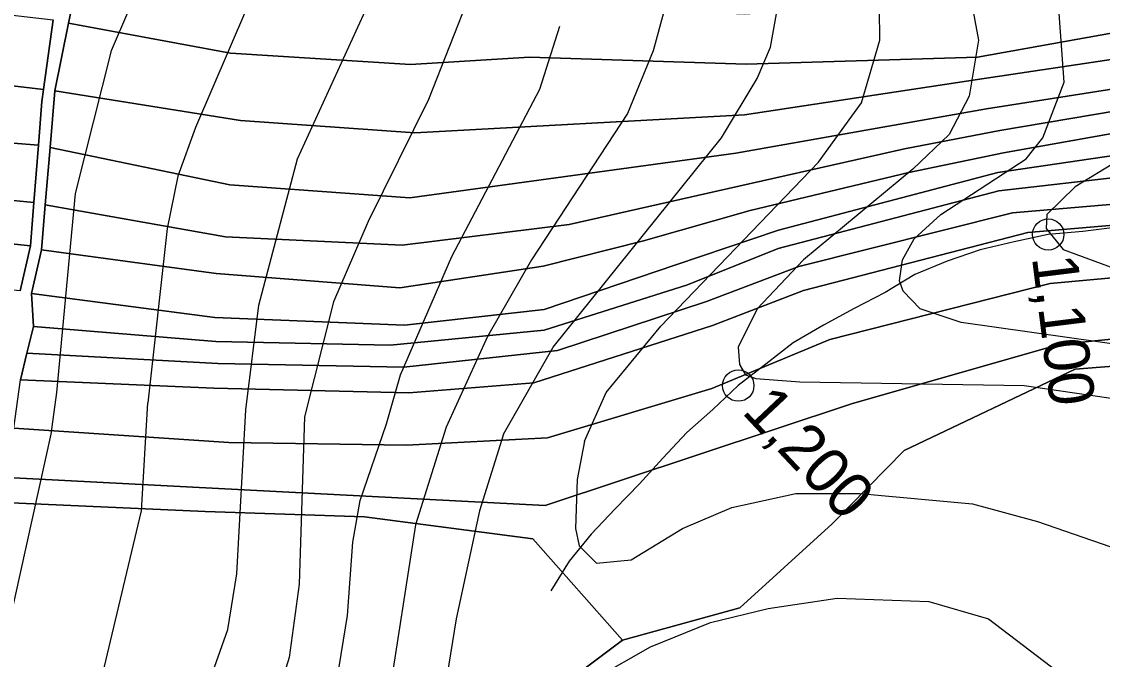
# Model space of a CAD drawing. Extents: x -510989 to -501240, y -1184665 to -1176098.
# Drawn here: x -510646.9 to -510337, y -1180937.6 to -1180754.7 of the extents above; entities that cross this region are included whole.
import ezdxf

# ---------------------------------------------------------------- set-up
doc = ezdxf.new("R2010")
doc.units = 0
for name, color, linetype in [('lesni_pozemek', 7, 'Continuous'), ('ostatni_plocha_x_ostatni_komunikace', 7, 'Continuous'), ('trasovani_toku', 7, 'Continuous'), ('vrstevnice_01', 7, 'Continuous'), ('vrstevnice_02', 7, 'Continuous')]:
    doc.layers.add(name, color=color, linetype=linetype)

msp = doc.modelspace()

# ---------------------------------------------------------------- linework, layer by layer
at = {"layer": 'lesni_pozemek'}
for points in [[(-510333.96, -1180757.86), (-510372.8, -1180764.87), (-510439.15, -1180766.86), (-510501.25, -1180764.87), (-510535.35, -1180767), (-510587, -1180763.69), (-510633.43, -1180755.12), (-510630.61, -1180741.23), (-510584.22, -1180746.54), (-510500.84, -1180749.96), (-510439.58, -1180752.46), (-510376.49, -1180748.63), (-510329.89, -1180740.89)], [(-510326.24, -1180764.25), (-510372.87, -1180771.28), (-510439.64, -1180781.36), (-510534.17, -1180786.58), (-510584.11, -1180783.03), (-510637.37, -1180774.48), (-510633.43, -1180755.12), (-510587, -1180763.69), (-510535.35, -1180767), (-510501.25, -1180764.87), (-510439.15, -1180766.86), (-510372.8, -1180764.87), (-510333.96, -1180757.86)], [(-510317.28, -1180771.36), (-510370.26, -1180779.68), (-510442.11, -1180792.41), (-510535.6, -1180805.23), (-510587.18, -1180801.43), (-510638.74, -1180790.8), (-510637.37, -1180774.48), (-510584.11, -1180783.03), (-510534.17, -1180786.58), (-510439.64, -1180781.36), (-510372.87, -1180771.28), (-510326.24, -1180764.25)], [(-510326.3, -1180779.13), (-510366.46, -1180785.85), (-510393.75, -1180791.1), (-510441.24, -1180801.85), (-510489.86, -1180812.86), (-510537.82, -1180818.75), (-510588.43, -1180816.35), (-510640.11, -1180807.17), (-510638.74, -1180790.8), (-510587.18, -1180801.43), (-510535.6, -1180805.23), (-510442.11, -1180792.41), (-510370.26, -1180779.68), (-510317.28, -1180771.36)], [(-510331.53, -1180786.23), (-510365.42, -1180792.33), (-510392.48, -1180797.95), (-510438, -1180808.85), (-510468.55, -1180817.53), (-510497.35, -1180824.82), (-510538.42, -1180830.98), (-510591.11, -1180826.91), (-510641.2, -1180820.14), (-510640.11, -1180807.17), (-510588.43, -1180816.35), (-510537.82, -1180818.75), (-510489.86, -1180812.86), (-510441.24, -1180801.85), (-510393.75, -1180791.1), (-510366.46, -1180785.85), (-510326.3, -1180779.13)], [(-510329.89, -1180792.47), (-510366.98, -1180797.95), (-510429.85, -1180814.43), (-510459.35, -1180824.43), (-510497.07, -1180837.22), (-510537.16, -1180841.72), (-510591.53, -1180839.52), (-510644.05, -1180832.61), (-510641.2, -1180820.14), (-510591.11, -1180826.91), (-510538.42, -1180830.98), (-510497.35, -1180824.82), (-510468.55, -1180817.53), (-510438, -1180808.85), (-510392.48, -1180797.95), (-510365.42, -1180792.33), (-510331.53, -1180786.23)], [(-510310.84, -1180796.76), (-510366.74, -1180803.21), (-510430.02, -1180819.69), (-510456.02, -1180830.17), (-510497.05, -1180843.13), (-510541.18, -1180847.42), (-510591.24, -1180846.41), (-510643.5, -1180842.09), (-510644.05, -1180832.61), (-510591.53, -1180839.52), (-510537.16, -1180841.72), (-510497.07, -1180837.22), (-510459.35, -1180824.43), (-510429.85, -1180814.43), (-510366.98, -1180797.95), (-510329.89, -1180792.47)], [(-510514.43, -1181142.06), (-510517.98, -1181134.4), (-510508.44, -1181129.48), (-510404.8, -1181065.45), (-510385.65, -1181068.79), (-510371.58, -1181065.33), (-510393.83, -1181031.6), (-510459.24, -1181070.48), (-510481.08, -1181080.51), (-510502.03, -1181079.72), (-510527.59, -1181080.7), (-510537.43, -1181072.51), (-510537.49, -1181058.5), (-510515.88, -1181037.1), (-510514.5, -1181030.02), (-510499.76, -1181009.72), (-510504.99, -1180978.68), (-510510.55, -1180959.04), (-510474.66, -1180932.03), (-510440.93, -1180922.79), (-510414.47, -1180898.71), (-510393.89, -1180877.67), (-510344.82, -1180854.38), (-510289.06, -1180849.97)], [(-510652, -1180892.55), (-510594.26, -1180895.19), (-510548.57, -1180896.69), (-510500.31, -1180903.02), (-510474.66, -1180932.03), (-510510.55, -1180959.04), (-510504.99, -1180978.68), (-510499.76, -1181009.72), (-510514.5, -1181030.02), (-510515.88, -1181037.1), (-510537.49, -1181058.5), (-510537.43, -1181072.51), (-510527.59, -1181080.7), (-510502.03, -1181079.72), (-510481.08, -1181080.51), (-510459.24, -1181070.48), (-510393.83, -1181031.6), (-510371.58, -1181065.33), (-510385.65, -1181068.79), (-510404.8, -1181065.45), (-510508.44, -1181129.48), (-510517.98, -1181134.4), (-510514.43, -1181142.06)]]:
    msp.add_lwpolyline(points, dxfattribs=at)
for points in [[(-510689.28, -1180748.14), (-510637.81, -1180754.19), (-510640.58, -1180774.09), (-510688.39, -1180768.49)], [(-510688.18, -1180773.2), (-510688.39, -1180768.49), (-510640.58, -1180774.09), (-510641.06, -1180777.54), (-510642.06, -1180790.1), (-510690.23, -1180786.24)], [(-510083.86, -1180780.95), (-510087.2, -1180785.84), (-510092.01, -1180791.3), (-510135.1, -1180793.22), (-510181.81, -1180796.4), (-510246.56, -1180799.57), (-510362.75, -1180809.46), (-510424.09, -1180824.9), (-510450.56, -1180834.94), (-510493.29, -1180848.99), (-510537.28, -1180853.76), (-510590.68, -1180852.68), (-510645.38, -1180849.79), (-510643.5, -1180842.09), (-510591.24, -1180846.41), (-510541.18, -1180847.42), (-510497.05, -1180843.13), (-510456.02, -1180830.17), (-510430.02, -1180819.69), (-510366.74, -1180803.21), (-510310.84, -1180796.76), (-510251.52, -1180791.01), (-510187.68, -1180788.81), (-510136.65, -1180785.5)], [(-510690.23, -1180786.24), (-510642.06, -1180790.1), (-510643.37, -1180806.5), (-510692.67, -1180801.79)], [(-510092.07, -1180791.37), (-510093.08, -1180792.66), (-510094.49, -1180794.45), (-510097.88, -1180798.76), (-510183.93, -1180803.19), (-510246.73, -1180805.6), (-510358.36, -1180815.11), (-510422.69, -1180831.74), (-510448.85, -1180841.81), (-510500.01, -1180858.29), (-510535.85, -1180861.12), (-510591.76, -1180859.76), (-510647.26, -1180857.42), (-510645.38, -1180849.79), (-510590.68, -1180852.68), (-510537.28, -1180853.76), (-510493.29, -1180848.99), (-510450.56, -1180834.94), (-510424.09, -1180824.9), (-510362.75, -1180809.46), (-510246.56, -1180799.57), (-510181.81, -1180796.4), (-510135.1, -1180793.22), (-510092.01, -1180791.3)], [(-510097.88, -1180798.76), (-510105.89, -1180808.96), (-510110.33, -1180814.6), (-510111.28, -1180814.69), (-510144.01, -1180817.74), (-510168.24, -1180817.57), (-510226.42, -1180819.08), (-510281.07, -1180823.3), (-510352.02, -1180829.82), (-510415.17, -1180845.81), (-510448.99, -1180859.86), (-510496.11, -1180874.04), (-510536.55, -1180876.1), (-510587.44, -1180875.37), (-510649.14, -1180871.3), (-510647.26, -1180857.42), (-510591.76, -1180859.76), (-510535.85, -1180861.12), (-510500.01, -1180858.29), (-510448.85, -1180841.81), (-510422.69, -1180831.74), (-510358.36, -1180815.11), (-510246.73, -1180805.6), (-510183.93, -1180803.19)], [(-510643.37, -1180806.5), (-510644.37, -1180818.98), (-510694.54, -1180813.7), (-510692.67, -1180801.79)], [(-510694.54, -1180813.7), (-510644.37, -1180818.98), (-510647.33, -1180831.84), (-510696.68, -1180827.28)], [(-510111.28, -1180814.69), (-510117.56, -1180832.73), (-510228.98, -1180834.99), (-510284.05, -1180840.6), (-510349.44, -1180847.27), (-510408.67, -1180864.16), (-510496.83, -1180893.47), (-510651.04, -1180885.39), (-510649.14, -1180871.3), (-510587.44, -1180875.37), (-510536.55, -1180876.1), (-510496.11, -1180874.04), (-510448.99, -1180859.86), (-510415.17, -1180845.81), (-510352.02, -1180829.82), (-510281.07, -1180823.3), (-510226.42, -1180819.08), (-510168.24, -1180817.57), (-510144.01, -1180817.74)], [(-510117.56, -1180832.73), (-510130.49, -1180841.99), (-510139.22, -1180844.61), (-510162.73, -1180843.17), (-510222.3, -1180843.41), (-510265.47, -1180846.19), (-510289.06, -1180849.97), (-510344.82, -1180854.38), (-510393.89, -1180877.67), (-510414.47, -1180898.71), (-510440.93, -1180922.79), (-510474.66, -1180932.03), (-510500.31, -1180903.02), (-510548.57, -1180896.69), (-510594.26, -1180895.19), (-510652, -1180892.55), (-510651.04, -1180885.39), (-510496.83, -1180893.47), (-510408.67, -1180864.16), (-510349.44, -1180847.27), (-510284.05, -1180840.6), (-510228.98, -1180834.99)]]:
    msp.add_lwpolyline(points, close=True, dxfattribs=at)
at = {"layer": 'ostatni_plocha_x_ostatni_komunikace'}
for points in [[(-510630.61, -1180741.23), (-510633.43, -1180755.12), (-510637.37, -1180774.48), (-510638.74, -1180790.8), (-510640.11, -1180807.17), (-510641.2, -1180820.14), (-510644.05, -1180832.61), (-510643.5, -1180842.09), (-510645.38, -1180849.79), (-510647.26, -1180857.42)], [(-510647.33, -1180831.84), (-510644.37, -1180818.98), (-510643.37, -1180806.5), (-510642.06, -1180790.1), (-510641.06, -1180777.54), (-510640.58, -1180774.09), (-510637.81, -1180754.19)]]:
    msp.add_lwpolyline(points, dxfattribs=at)
at = {"layer": 'trasovani_toku'}
for p, q in [((-510342.6, -1180814.84), (-510352.56, -1180815.71)), ((-510332.67, -1180813.66), (-510342.6, -1180814.84)), ((-510362.33, -1180817.85), (-510372.06, -1180820.15)), ((-510352.56, -1180815.71), (-510362.33, -1180817.85)), ((-510372.06, -1180820.15), (-510381.53, -1180823.36)), ((-510381.53, -1180823.36), (-510390.76, -1180827.22)), ((-510390.76, -1180827.22), (-510399.35, -1180832.34)), ((-510399.35, -1180832.34), (-510408.2, -1180836.99)), ((-510408.2, -1180836.99), (-510417.02, -1180841.71)), ((-510417.02, -1180841.71), (-510425.64, -1180846.77)), ((-510425.64, -1180846.77), (-510433.5, -1180852.95)), ((-510433.5, -1180852.95), (-510441.43, -1180859.05)), ((-510441.43, -1180859.05), (-510448.72, -1180865.89)), ((-510448.72, -1180865.89), (-510456.2, -1180872.53)), ((-510456.2, -1180872.53), (-510463.02, -1180879.85)), ((-510463.02, -1180879.85), (-510469.75, -1180887.24)), ((-510469.75, -1180887.24), (-510476.71, -1180894.42)), ((-510476.71, -1180894.42), (-510483.57, -1180901.7)), ((-510483.57, -1180901.7), (-510489.95, -1180909.4)), ((-510489.95, -1180909.4), (-510495.19, -1180917.91))]:
    msp.add_line(p, q, dxfattribs=at)
for centre in [(-510352.56, -1180815.71), (-510441.43, -1180859.05)]:
    msp.add_circle(centre, 4.5, dxfattribs=at)
at = {"layer": 'vrstevnice_01'}
for points in [[(-510582.59, -1180866), (-510578.91, -1180836), (-510567.81, -1180794), (-510546.81, -1180748), (-510531.19, -1180695), (-510523, -1180676), (-510516.19, -1180666), (-510494.59, -1180637), (-510486.59, -1180623), (-510480.19, -1180603), (-510471, -1180558)], [(-510549.5, -1180565), (-510550.19, -1180590), (-510553.81, -1180608), (-510561.5, -1180625), (-510580.81, -1180660), (-510590.19, -1180682), (-510601.09, -1180716), (-510621.19, -1180763), (-510631.5, -1180804), (-510636.91, -1180861)], [(-510508.69, -1180873), (-510494.5, -1180848), (-510446.19, -1180788), (-510436, -1180771), (-510432.19, -1180762), (-510429.5, -1180747), (-510432.19, -1180724), (-510429.69, -1180710), (-510410.31, -1180669), (-510400.91, -1180656), (-510391, -1180651), (-510381.09, -1180651), (-510365, -1180658), (-510335.5, -1180675)], [(-510310.5, -1180727), (-510337.19, -1180717), (-510363.59, -1180705), (-510372.59, -1180703), (-510381.81, -1180704), (-510384.59, -1180707), (-510386.81, -1180713), (-510386.09, -1180719), (-510375.69, -1180743), (-510372.59, -1180760), (-510375.19, -1180776), (-510381, -1180787), (-510391.41, -1180797), (-510422.69, -1180823), (-510436, -1180837), (-510441.41, -1180848), (-510441.09, -1180853), (-510439.31, -1180856), (-510436.41, -1180857), (-510423.81, -1180858), (-510359.41, -1180859), (-510325.31, -1180864)], [(-510542.31, -1180870), (-510538.31, -1180856), (-510523.5, -1180822), (-510498.31, -1180774), (-510492.54, -1180755.96)], [(-510329.91, -1180793), (-510344.81, -1180802), (-510352.91, -1180810), (-510353.19, -1180814), (-510348.31, -1180820), (-510331.91, -1180826)], [(-510636.91, -1180861), (-510638.5, -1180873), (-510650.69, -1180928), (-510659.5, -1180947), (-510675, -1180972), (-510681.41, -1180987), (-510693.09, -1181020), (-510700.09, -1181035), (-510707.5, -1181059), (-510709.31, -1181087), (-510705.81, -1181106), (-510699.81, -1181122), (-510689.91, -1181139)], [(-510594.81, -1180949), (-510587.81, -1180929), (-510585.19, -1180913), (-510582.59, -1180866)], [(-510558.81, -1180958), (-510553.5, -1180925), (-510551.91, -1180904), (-510549.81, -1180892), (-510542.31, -1180870)], [(-510508.69, -1180873), (-510515.59, -1180895), (-510522.31, -1180926), (-510528.09, -1180962), (-510535.31, -1180981), (-510536.31, -1180989), (-510534.19, -1180991), (-510529.19, -1180991), (-510518, -1180983), (-510499, -1180957), (-510482.31, -1180943), (-510466.59, -1180934), (-510449.41, -1180927), (-510432.81, -1180923), (-510413.09, -1180920), (-510386.81, -1180921), (-510369.69, -1180926), (-510350, -1180941), (-510340.69, -1180962), (-510323.31, -1181047)]]:
    msp.add_lwpolyline(points, dxfattribs=at)
at = {"layer": 'vrstevnice_02'}
for points in [[(-510514.31, -1180579), (-510517.91, -1180603), (-510523.19, -1180618), (-510548.09, -1180659), (-510562.59, -1180688), (-510577.69, -1180740), (-510597, -1180785), (-510602.09, -1180799), (-510605.19, -1180814), (-510610.69, -1180864)], [(-510262.5, -1180577), (-510271.91, -1180585), (-510285.91, -1180601), (-510301.41, -1180624), (-510309.41, -1180632), (-510315.59, -1180636), (-510324.09, -1180638), (-510333.91, -1180636), (-510363.19, -1180626), (-510386.09, -1180621), (-510399.91, -1180624), (-510406.19, -1180626), (-510414.59, -1180633), (-510429.69, -1180659), (-510447.41, -1180693), (-510453.81, -1180708), (-510459, -1180738), (-510465.81, -1180763), (-510473.19, -1180781), (-510500.69, -1180823), (-510513.31, -1180845), (-510525.19, -1180871)], [(-510447.59, -1180580), (-510462.31, -1180626), (-510476.31, -1180655), (-510495.69, -1180684), (-510510.41, -1180720), (-510512.19, -1180731), (-510530.19, -1180777), (-510547.5, -1180812), (-510557.5, -1180835), (-510565.81, -1180868)], [(-510485.5, -1180875), (-510479.31, -1180861), (-510463.59, -1180842), (-510418.41, -1180795), (-510406.09, -1180778), (-510400.81, -1180760), (-510400.91, -1180751), (-510407.81, -1180728), (-510408.31, -1180711), (-510406.5, -1180704), (-510397.69, -1180687), (-510390.41, -1180679), (-510379, -1180675), (-510365.41, -1180680), (-510337.19, -1180695), (-510322.69, -1180701)], [(-510306.59, -1180851), (-510377.5, -1180841), (-510389.31, -1180837), (-510394.19, -1180832), (-510395.19, -1180829), (-510394.31, -1180823), (-510391, -1180817), (-510383.31, -1180810), (-510358.91, -1180794), (-510354.09, -1180788), (-510348, -1180772), (-510349.81, -1180747), (-510348, -1180741), (-510345.09, -1180739), (-510336, -1180740)], [(-510540.91, -1181140), (-510612.5, -1181135), (-510644.81, -1181139), (-510661.59, -1181135), (-510670.09, -1181126), (-510675.59, -1181113), (-510677.81, -1181103), (-510679.59, -1181084), (-510672, -1181058), (-510656.31, -1181024), (-510644.09, -1180987), (-510630.41, -1180959), (-510623.19, -1180940), (-510612.5, -1180895), (-510610.69, -1180864)], [(-510565.81, -1180868), (-510567.31, -1180916), (-510570.19, -1180937), (-510573.91, -1180949)], [(-510525.19, -1180871), (-510534, -1180899), (-510541.91, -1180950)], [(-510485.5, -1180875), (-510487.59, -1180886), (-510488.09, -1180900), (-510487, -1180905), (-510482.09, -1180910), (-510472.09, -1180909), (-510457.41, -1180900), (-510443.31, -1180894), (-510424.91, -1180890), (-510406.59, -1180890), (-510374.31, -1180893), (-510355.59, -1180898), (-510329.59, -1180907)]]:
    msp.add_lwpolyline(points, dxfattribs=at)

# ---------------------------------------------------------------- texts
at = {"layer": 'trasovani_toku'}
for s, rotation, p in [('1,100', 277.1221, (-510357.24, -1180822.29)), ('1,200', 313.3131, (-510440.68, -1180866.76))]:
    msp.add_text(s, height=13, rotation=rotation, dxfattribs=at).set_placement(p)

doc.saveas('drawing.dxf')
